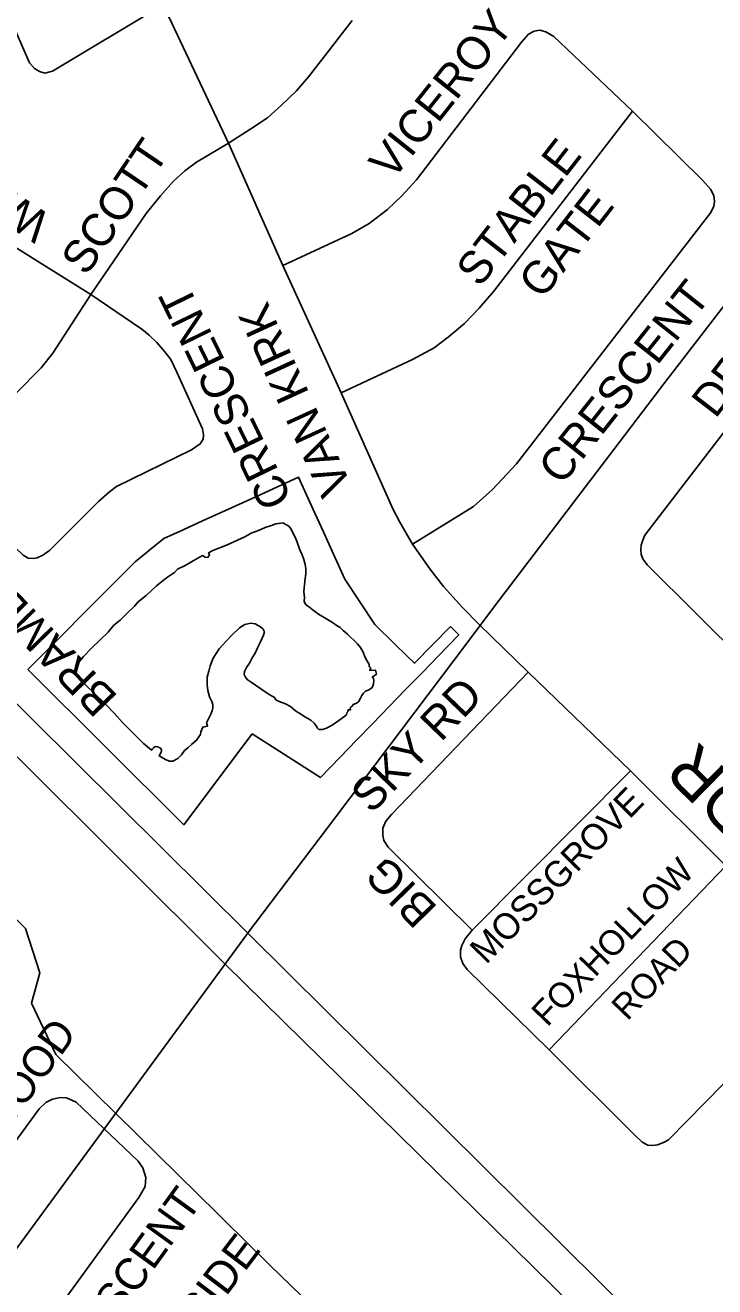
# Model space of a CAD drawing. Extents: x 586326 to 623965, y 4819854 to 4857850.
# Drawn here: x 595024 to 595381, y 4840357 to 4841010 of the extents above; entities that cross this region are included whole.
import ezdxf

# ---------------------------------------------------------------- set-up
doc = ezdxf.new("R2010")
doc.units = 0
for name, color, linetype in [('Lots_Concessions', 7, 'Continuous'), ('Major Rds and Hwys', 7, 'Continuous'), ('Minor Rd Lbls', 7, 'Continuous'), ('Minor Rds', 7, 'Continuous'), ('Park Outlines', 7, 'Continuous'), ('Proposed Secondary Rds', 7, 'Continuous'), ('Secondary Rds Lbls', 7, 'Continuous'), ('SWM Ponds', 7, 'Continuous')]:
    doc.layers.add(name, color=color, linetype=linetype)

msp = doc.modelspace()

# ---------------------------------------------------------------- linework, layer by layer
at = {"layer": 'Lots_Concessions'}
for p, q in [((595355.33, 4840825.3), (595449.65, 4840947.73)), ((595266.78, 4840708.87), (595355.33, 4840825.3)), ((595252.8, 4840690.38), (595266.78, 4840708.87)), ((595184.67, 4840600.27), (595252.8, 4840690.38)), ((595138.79, 4840539.51), (595184.67, 4840600.27)), ((594913.9, 4840233.24), (595138.87, 4840539.78))]:
    msp.add_line(p, q, dxfattribs=at)
at = {"layer": 'Major Rds and Hwys'}
msp.add_lwpolyline([(595383.41, 4840297.88), (595139.32, 4840539.74), (594937.57, 4840739.64)], dxfattribs=at)
at = {"layer": 'Minor Rds'}
for points in [[(595095.16, 4841021.04), (595037.85, 4840986.63), (595033.85, 4840985.59), (595030.98, 4840986.47), (595028.55, 4840988.09), (595025.89, 4840990.99), (595001.93, 4841045.31), (595001.08, 4841048.43), (595001.03, 4841051.35), (595001.19, 4841053.83), (595002.57, 4841056.99), (595031.01, 4841093.23), (595035.33, 4841097.52), (595039.64, 4841100.59), (595046.81, 4841104.16), (595057.41, 4841108.8)], [(595129, 4840949.32), (595140.69, 4840956.75), (595149.28, 4840962.49), (595156.62, 4840969.08), (595164.32, 4840976.48), (595170.59, 4840983.63), (595180.33, 4840996.18), (595193.2, 4841012.92)], [(595157.26, 4840885.95), (595192.99, 4840902.48), (595202.08, 4840907.67), (595211.49, 4840914.98), (595218.94, 4840922.05), (595226.58, 4840930.3), (595281.01, 4841001.69), (595284.67, 4841005.79), (595287.55, 4841007.4), (595290.64, 4841007.94), (595293.75, 4841006.99), (595297.88, 4841004.51), (595338.64, 4840965.85)], [(595187.48, 4840819.97), (595224.46, 4840837.15), (595235.76, 4840843.28), (595243.07, 4840848.83), (595251.43, 4840855.93), (595259.03, 4840863.76), (595266.68, 4840872.6), (595338.64, 4840965.85)], [(595224.48, 4840741.43), (595256.08, 4840761.02), (595266.08, 4840769.76), (595278.45, 4840783.17), (595379.18, 4840913.32), (595380.77, 4840916.64), (595381.13, 4840919.08), (595380.81, 4840922.18), (595379.03, 4840925.4), (595374.97, 4840930.06), (595338.64, 4840965.85)], [(595057.7, 4840870.86), (595086.35, 4840912.95), (595093.76, 4840922.09), (595100.31, 4840929.43), (595106.4, 4840934.94), (595112.44, 4840939.52), (595129, 4840949.32)], [(595057.7, 4840870.86), (594996.09, 4840909.3)], [(594978.86, 4840779.42), (595018.45, 4840739.75), (595022.64, 4840735.73), (595025.19, 4840734.26), (595027.71, 4840734.07), (595029.9, 4840734.51), (595032.79, 4840735.73), (595036.3, 4840738.24), (595061.74, 4840763.57), (595067.45, 4840768.61), (595071.01, 4840771.41), (595109.96, 4840790.42), (595114.42, 4840793.44), (595115.86, 4840795.85), (595116.1, 4840798.23), (595115.66, 4840801.32), (595102.31, 4840830.59), (595099.12, 4840837.23), (595096.1, 4840841.22), (595091.88, 4840846.07), (595087.93, 4840849.82), (595084.18, 4840852.9), (595079.29, 4840856.21), (595057.7, 4840870.86)], [(594978.86, 4840779.42), (595031.84, 4840832.83), (595037.95, 4840840.56), (595057.7, 4840870.86)], [(595574.76, 4840504.01), (595346.22, 4840730.76), (595343.97, 4840733.89), (595343.17, 4840736.17), (595343, 4840738.54), (595343.06, 4840741.01), (595343.91, 4840743.67), (595345.1, 4840746.12), (595388.57, 4840802.86)], [(595255.49, 4840541.41), (595211.86, 4840584.43), (595209.73, 4840587.97), (595209.06, 4840590.8), (595209.06, 4840594.4), (595210.76, 4840597.97), (595213.54, 4840601.42), (595284.52, 4840675.12)], [(595255.49, 4840541.41), (595337.64, 4840624.06)], [(595295.48, 4840479.45), (595387.09, 4840574.86)], [(595295.48, 4840479.45), (595252.92, 4840521.16), (595250.68, 4840524.2), (595249.45, 4840527.69), (595249.4, 4840531.04), (595250.06, 4840533.55), (595251.82, 4840537), (595255.49, 4840541.41)], [(595295.48, 4840479.45), (595339.4, 4840435.61), (595343.55, 4840431.61), (595346.62, 4840430.01), (595349.18, 4840429.96), (595351.6, 4840430.29), (595354.7, 4840431.4), (595357.23, 4840432.89), (595442.7, 4840519.79)], [(595015.77, 4840311.29), (595082.61, 4840402.98), (595085.78, 4840408.64), (595086.14, 4840413.37), (595084.59, 4840418.33), (595082.29, 4840421.79), (595050.08, 4840452.38), (595045, 4840454.68), (595041.71, 4840454.75), (595037.72, 4840453.91), (595034.3, 4840452.2), (595030.95, 4840448.98), (594985.53, 4840386.87), (594960.44, 4840352.58)]]:
    msp.add_lwpolyline(points, dxfattribs=at)
at = {"layer": 'Park Outlines'}
msp.add_lwpolyline([(595025.09, 4840676.61), (595105.94, 4840596.14), (595141.44, 4840643.15), (595176.8, 4840620.64), (595186.99, 4840631.15), (595195.48, 4840639.9), (595203.97, 4840648.66), (595212.46, 4840657.41), (595220.96, 4840666.17), (595229.45, 4840674.92), (595237.94, 4840683.68), (595248.52, 4840694.59), (595244.21, 4840698.82), (595225.51, 4840679.78), (595221.73, 4840683.49), (595215.05, 4840690.05), (595204.97, 4840699.95), (595197.16, 4840711.71), (595189.37, 4840723.45), (595183.55, 4840736.29), (595178.16, 4840748.17), (595172.99, 4840759.55), (595167.83, 4840770.93), (595165.46, 4840776.15), (595143.69, 4840766.27), (595125.64, 4840758.08), (595115.62, 4840753.54), (595105.61, 4840748.99), (595095.6, 4840744.45), (595088.25, 4840738.54), (595080.64, 4840732.42), (595072.88, 4840724.62), (595065.12, 4840716.83), (595057.36, 4840709.03), (595040.07, 4840691.65), (595027.21, 4840678.74)], close=True, dxfattribs=at)
for points in [[(595347.02, 4840308.12), (595127.38, 4840523.95), (595019.43, 4840631.38)], [(595010.86, 4840555.28), (595023.77, 4840542.42), (595031.17, 4840519.4), (595026.87, 4840503.65), (595039.56, 4840477.01), (595070.57, 4840446.55), (595070.78, 4840446.35), (595102.95, 4840414.73), (595123.13, 4840394.91), (595126.3, 4840391.78), (595150.55, 4840367.96), (595166.88, 4840351.92)]]:
    msp.add_lwpolyline(points, dxfattribs=at)
at = {"layer": 'Proposed Secondary Rds'}
for points in [[(595095.16, 4841021.04), (595129, 4840949.32)], [(595129, 4840949.32), (595157.26, 4840885.95)], [(595157.26, 4840885.95), (595187.48, 4840819.97)], [(595187.48, 4840819.97), (595214.25, 4840759.8), (595217.92, 4840752.93), (595224.48, 4840741.43)], [(595284.52, 4840675.12), (595259.02, 4840699.93), (595250.37, 4840708.77), (595240.57, 4840719.62), (595233.53, 4840728.74), (595224.48, 4840741.43)], [(595337.64, 4840624.06), (595284.52, 4840675.12)], [(595387.09, 4840574.86), (595337.64, 4840624.06)]]:
    msp.add_lwpolyline(points, dxfattribs=at)
at = {"layer": 'SWM Ponds'}
msp.add_lwpolyline([(595065.48, 4840658.37), (595069.72, 4840653.95), (595074.14, 4840649.13), (595080.11, 4840643.04), (595084.85, 4840638.46), (595089.11, 4840634.7), (595089.68, 4840635.44), (595090.33, 4840636.11), (595091.14, 4840636.59), (595092.29, 4840636.56), (595093.17, 4840636.18), (595093.84, 4840635.73), (595094.33, 4840634.96), (595094.28, 4840634.26), (595094.05, 4840633.57), (595093.57, 4840632.64), (595093.05, 4840631.81), (595094.42, 4840631.11), (595096.45, 4840629.9), (595098.29, 4840629.08), (595100.25, 4840629.04), (595102.78, 4840630.53), (595104.71, 4840632.37), (595106.18, 4840634.57), (595107.97, 4840635.91), (595109.9, 4840637.75), (595112.49, 4840639.94), (595114.64, 4840642.85), (595114.67, 4840644.32), (595115.76, 4840646.73), (595118.22, 4840647.12), (595117.73, 4840648.87), (595118.89, 4840651.31), (595119.95, 4840653.46), (595120.65, 4840655.15), (595120.88, 4840656.71), (595120.95, 4840658.39), (595120.39, 4840660.06), (595119.27, 4840662.43), (595118.31, 4840665.66), (595118.08, 4840668.69), (595118.1, 4840672.53), (595118.89, 4840675.76), (595119.66, 4840678.5), (595121.07, 4840682.36), (595124.16, 4840687.27), (595127.65, 4840691.11), (595130.93, 4840694.5), (595134.73, 4840698.11), (595137.58, 4840699.85), (595140.63, 4840700.57), (595142.83, 4840700.21), (595145.66, 4840698.75), (595147.06, 4840697.53), (595147.72, 4840696.15), (595147.31, 4840694.36), (595146.36, 4840692.5), (595145.55, 4840690.52), (595144.37, 4840688.22), (595143.05, 4840685.41), (595141.15, 4840682.18), (595139.97, 4840679.88), (595138.38, 4840677.52), (595137.3, 4840675.51), (595137.21, 4840673.97), (595137.87, 4840672.59), (595138.72, 4840671.3), (595140.77, 4840669.95), (595143.11, 4840668.49), (595145.78, 4840666.52), (595149.72, 4840663.94), (595152.87, 4840662.1), (595153.57, 4840660.93), (595155.43, 4840659.98), (595158.58, 4840658.76), (595161.19, 4840657.34), (595163.9, 4840655.1), (595166.08, 4840653.77), (595169.1, 4840651.91), (595171.8, 4840650.29), (595173.51, 4840648.83), (595174.52, 4840647.42), (595175.3, 4840646.19), (595176.02, 4840645.45), (595177.79, 4840645.49), (595179.93, 4840646.17), (595182.89, 4840647.65), (595186.24, 4840650.11), (595189.4, 4840652.42), (595190.33, 4840653.12), (595190.51, 4840654.15), (595191.01, 4840654.63), (595190.99, 4840655.08), (595191.35, 4840655.68), (595192.31, 4840655.66), (595192.19, 4840656.69), (595192.75, 4840657.18), (595193.32, 4840657.67), (595193.71, 4840658.48), (595195.05, 4840658.92), (595196.27, 4840659.7), (595196.63, 4840659.92), (595196.91, 4840660.51), (595197.49, 4840661.73), (595198.2, 4840663.04), (595199.05, 4840664.29), (595200.22, 4840665.3), (595201.46, 4840665.94), (595202.71, 4840666.58), (595203.45, 4840667.06), (595203.86, 4840667.98), (595204.26, 4840669.21), (595204.51, 4840670.88), (595204.29, 4840671.86), (595203.98, 4840672.35), (595203.64, 4840672.62), (595205.85, 4840674.18), (595205.36, 4840676.17), (595202.37, 4840676.08), (595202.37, 4840676.4), (595202.86, 4840676.39), (595202.71, 4840677.06), (595202.76, 4840677.45), (595202.29, 4840677.88), (595202.04, 4840678.51), (595202.09, 4840679.29), (595201.57, 4840680.06), (595200.84, 4840681.19), (595199.87, 4840683.19), (595198.92, 4840685.48), (595197.61, 4840687.93), (595195.91, 4840689.88), (595194.43, 4840691.47), (595192.19, 4840693.53), (595190.81, 4840694.86), (595188.62, 4840696.82), (595186.94, 4840698.25), (595184.9, 4840699.6), (595183.04, 4840700.87), (595179.54, 4840702.98), (595175.82, 4840705.2), (595172.96, 4840707.26), (595171.22, 4840708.61), (595170.23, 4840709.32), (595169.4, 4840710.16), (595168.65, 4840710.87), (595168.34, 4840711.91), (595168.48, 4840713.91), (595168.21, 4840716.98), (595168.44, 4840720.52), (595168.77, 4840723.73), (595169.2, 4840726.19), (595169.19, 4840728.87), (595168.8, 4840730.91), (595168.16, 4840733.51), (595167.31, 4840735.91), (595166.15, 4840738.56), (595164.73, 4840742.53), (595163.66, 4840745.22), (595162.68, 4840746.97), (595162.08, 4840748.19), (595161.37, 4840749.43), (595160.48, 4840750.74), (595159.84, 4840751.12), (595159.07, 4840751.48), (595157.4, 4840752.52), (595156.17, 4840752.37), (595154.87, 4840752.14), (595153.64, 4840751.99), (595151.37, 4840751.16), (595148.09, 4840750.13), (595144.72, 4840748.67), (595140.78, 4840747.28), (595137.47, 4840745.27), (595128.12, 4840740.92), (595120.93, 4840738.23), (595118.71, 4840736.98), (595119.26, 4840735.93), (595118.38, 4840734.64), (595117.03, 4840734.82), (595115.68, 4840735.63), (595110.79, 4840732.87), (595106.56, 4840730.47), (595102.69, 4840728.54), (595101.01, 4840726.77), (595096.97, 4840724.07), (595091.77, 4840719.95), (595086.39, 4840714.98), (595082.2, 4840711.68), (595080.26, 4840709.35), (595076.45, 4840705.75), (595072.92, 4840702.18), (595069.62, 4840699.55), (595066.72, 4840695.99), (595062.35, 4840691.83), (595058.18, 4840687.77), (595053.93, 4840683.27), (595050.97, 4840679.64), (595049.74, 4840677.75), (595049.37, 4840676.17), (595049.34, 4840674.7), (595050.15, 4840673.2), (595052.46, 4840670.91), (595055.53, 4840668.01), (595059.17, 4840664.42)], close=True, dxfattribs=at)

# ---------------------------------------------------------------- texts
at = {"layer": 'Minor Rd Lbls'}
for s, height, rotation, p in [('VICEROY', 17, 51.54125, (595214.13, 4840929.45)), ('SCOTT', 17, 55.93109, (595055.39, 4840879.97)), ('STABLE ', 17, 52.14463, (595259.42, 4840874.04)), ('WAND', 17, 146.98221, (595037.94, 4840911.29)), ('GATE', 17, 52.20837, (595291.83, 4840867.83)), ('CRESCENT', 17, 51.54125, (595301.92, 4840771.45)), ('CRESCENT', 17, 115.92805, (595162.41, 4840764.82)), ('DRIVE', 17, 52.45939, (595381.6, 4840806.11)), ('VAN KIRK', 17, 114.62165, (595193.24, 4840771.43)), ('BRAMBIRCH', 17, 134.13359, (595072.26, 4840662.52)), ('SKY RD', 17, 46.09548, (595203.33, 4840601.32)), ('MOSSGROVE', 13.446, 45.39537, (595262.64, 4840523.31)), ('BIG', 17, 134.53973, (595238.1, 4840553.18)), ('FOXHOLLOW', 13, 46.1495, (595294.44, 4840490.9)), ('ROAD', 13, 46.1495, (595335.93, 4840494.05)), ('KNIGHTSWOOD', 15.9884, 54.00523, (594954.66, 4840355.48)), ('CRESCENT', 16.468, 54.07711, (595044.58, 4840302.26)), ('SANDYSIDE', 16.468, 52.77165, (595069.3, 4840274.39))]:
    msp.add_text(s, height=height, rotation=rotation, dxfattribs=at).set_placement(p)
at = {"layer": 'Secondary Rds Lbls'}
msp.add_text('VAN KIRK DR', height=25.002, rotation=135.52121, dxfattribs=at).set_placement((595524.32, 4840490.28))

doc.saveas('drawing.dxf')
